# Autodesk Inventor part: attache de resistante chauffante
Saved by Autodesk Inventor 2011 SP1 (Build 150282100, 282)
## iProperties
Created: 2010-12
Part Number: attache de resistante chauffante
Document SubType Name: Modeling
Designer: eric
Density: 1 g/cm^3
Author: eric
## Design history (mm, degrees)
feature "Base1"
node "Solide1"
node "Corps solides"
node "Corps surfaciques"
